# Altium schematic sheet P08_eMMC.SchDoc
size 386 x 246 mm
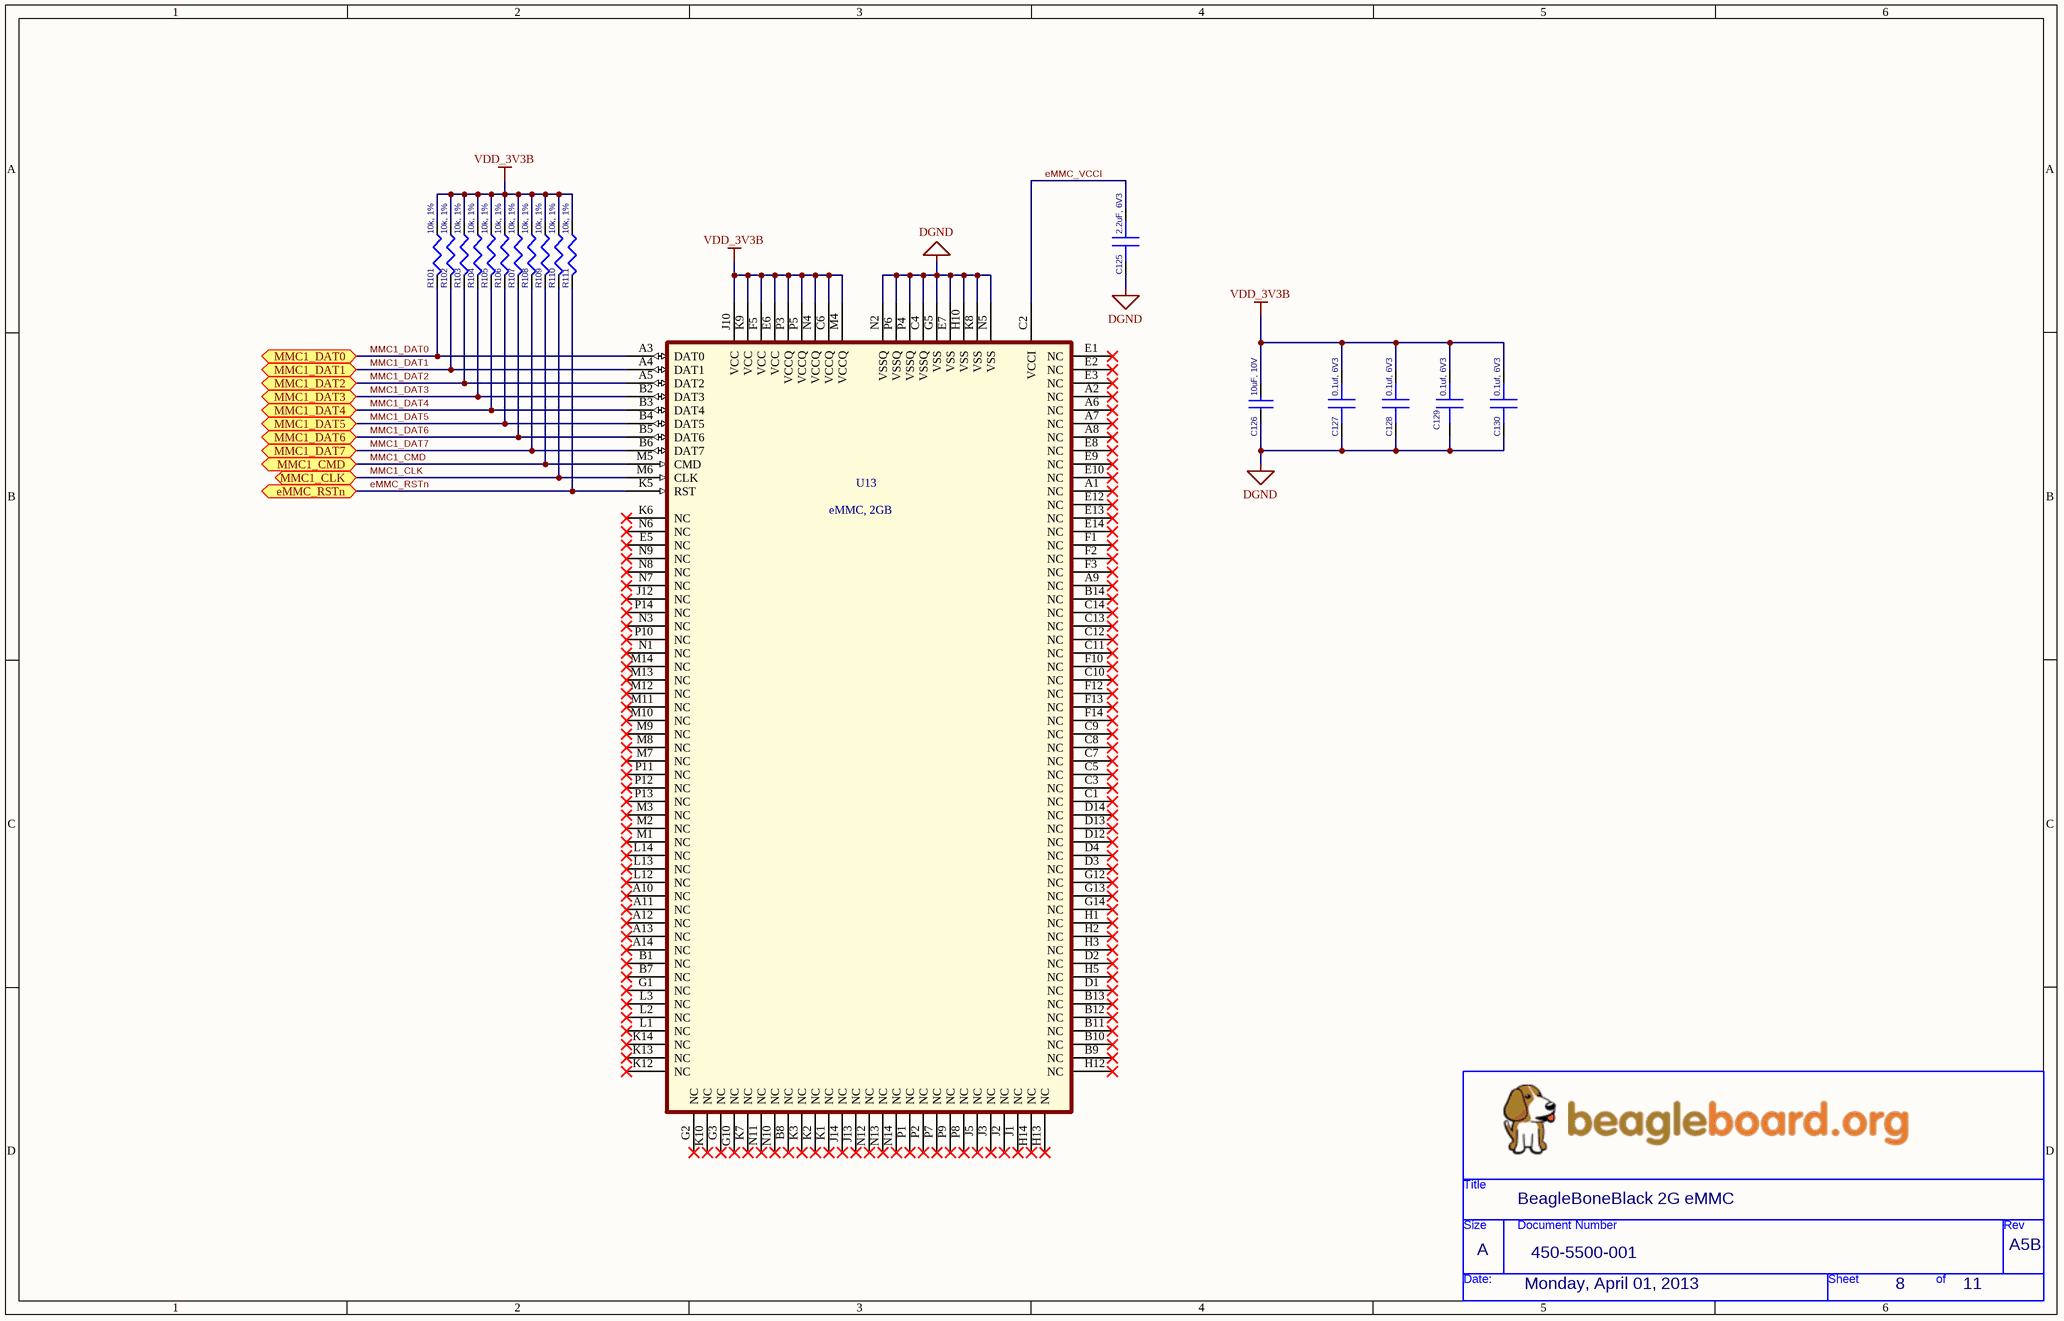
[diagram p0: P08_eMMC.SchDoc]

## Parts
*  Page Create Date: Monday, April 01, 2013  Doc: 450-5500-001  RevCode: A5B  Title: BeagleBoneBlack 2G eMMC  Page Size: A  Page Number: 8  Page Count: 11  (hidden comment: BeagleBoard_org)  (graphical)
C125  2.2uF, 6V3  [402]
C126  10uF, 10V  [805]
C127  0.1uf, 6V3  [402]
C128  0.1uf, 6V3  [402]
C129  0.1uf, 6V3  [402]
C130  0.1uf, 6V3  [402]
R101  10k, 1%  [402]
R102  10k, 1%  [402]
R103  10k, 1%  [402]
R104  10k, 1%  [402]
R105  10k, 1%  [402]
R106  10k, 1%  [402]
R107  10k, 1%  [402]
R108  10k, 1%  [402]
R109  10k, 1%  [402]
R110  10k, 1%  [402]
R111  10k, 1%  [402]
U13  eMMC, 2GB  [BGA153_P14_P5_11P5X13]

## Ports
eMMC_RSTn, MMC1_CLK, MMC1_CMD, MMC1_DAT0, MMC1_DAT1, MMC1_DAT2, MMC1_DAT3, MMC1_DAT4, MMC1_DAT5, MMC1_DAT6, MMC1_DAT7

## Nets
DGND: C125.2 C126.1 C127.2 C128.2 C129.2 C130.2 U13.C4(VSSQ) U13.E7(VSS) U13.G5(VSS) U13.H10(VSS) U13.K8(VSS) U13.N2(VSSQ) U13.N5(VSS) U13.P4(VSSQ) U13.P6(VSSQ)
VDD_3V3B: C126.2 C127.1 C128.1 C129.1 C130.1 R101.1 R102.1 R103.1 R104.1 R105.1 R106.1 R107.1 R108.1 R109.1 R110.1 R111.1 U13.C6(VCCQ) U13.E6(VCC) U13.F5(VCC) U13.J10(VCC) U13.K9(VCC) U13.M4(VCCQ) U13.N4(VCCQ) U13.P3(VCCQ) U13.P5(VCCQ)
eMMC_RSTn: R111.2 U13.K5(RST) ; port eMMC_RSTn
eMMC_VCCI: C125.1 U13.C2(VCCI)
MMC1_CLK: R110.2 U13.M6(CLK) ; port MMC1_CLK
MMC1_CMD: R109.2 U13.M5(CMD) ; port MMC1_CMD
MMC1_DAT0: R101.2 U13.A3(DAT0) ; port MMC1_DAT0
MMC1_DAT1: R102.2 U13.A4(DAT1) ; port MMC1_DAT1
MMC1_DAT2: R103.2 U13.A5(DAT2) ; port MMC1_DAT2
MMC1_DAT3: R104.2 U13.B2(DAT3) ; port MMC1_DAT3
MMC1_DAT4: R105.2 U13.B3(DAT4) ; port MMC1_DAT4
MMC1_DAT5: R106.2 U13.B4(DAT5) ; port MMC1_DAT5
MMC1_DAT6: R107.2 U13.B5(DAT6) ; port MMC1_DAT6
MMC1_DAT7: R108.2 U13.B6(DAT7) ; port MMC1_DAT7

Not connected (* = marked no-connect by the designer): U13 A1(NC)* A2(NC)* A6(NC)* A7(NC)* A8(NC)* A9(NC)* A10(NC)* A11(NC)* A12(NC)* A13(NC)* A14(NC)* B1(NC)* B7(NC)* B8(NC)* B9(NC)* B10(NC)* B11(NC)* B12(NC)* B13(NC)* B14(NC)* C1(NC)* C3(NC)* C5(NC)* C7(NC)* C8(NC)* C9(NC)* C10(NC)* C11(NC)* C12(NC)* C13(NC)* C14(NC)* D1(NC)* D2(NC)* D3(NC)* D4(NC)* D12(NC)* D13(NC)* D14(NC)* E1(NC)* E2(NC)* E3(NC)* E5(NC)* E8(NC)* E9(NC)* E10(NC)* E12(NC)* E13(NC)* E14(NC)* F1(NC)* F2(NC)* F3(NC)* F10(NC)* F12(NC)* F13(NC)* F14(NC)* G1(NC)* G2(NC)* G3(NC)* G10(NC)* G12(NC)* G13(NC)* G14(NC)* H1(NC)* H2(NC)* H3(NC)* H5(NC)* H12(NC)* H13(NC)* H14(NC)* J1(NC)* J2(NC)* J3(NC)* J5(NC)* J12(NC)* J13(NC)* J14(NC)* K1(NC)* K2(NC)* K3(NC)* K6(NC)* K7(NC)* K10(NC)* K12(NC)* K13(NC)* K14(NC)* L1(NC)* L2(NC)* L3(NC)* L12(NC)* L13(NC)* L14(NC)* M1(NC)* M2(NC)* M3(NC)* M7(NC)* M8(NC)* M9(NC)* M10(NC)* M11(NC)* M12(NC)* M13(NC)* M14(NC)* N1(NC)* N3(NC)* N6(NC)* N7(NC)* N8(NC)* N9(NC)* N10(NC)* N11(NC)* N12(NC)* N13(NC)* N14(NC)* P1(NC)* P2(NC)* P7(NC)* P8(NC)* P9(NC)* P10(NC)* P11(NC)* P12(NC)* P13(NC)* P14(NC)*

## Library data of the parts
C125 = CAP SMD: CAP CER 2.2UF 6.3V 10% X5R 0402; Manufacturer: TDK Corporation; Manufacturer Part Number: C1005X5R0J225K050BC; Capacitance: 2.2µF
C126 = CAP_4.7uF_X5R_6.3V_10%_0603: CAP CER 10UF 10V Y5V 0805; Manufacturer: TDK Corporation; Manufacturer Part Number: C2012Y5V1A106Z; Capacitance: 10µF; Tolerance: -20%, +80%; Temperature Coefficient: Y5V (F)
C127-C130 = CAP SMD: CAP CER 0.1UF 6.3V 10% X5R 0402; Manufacturer: TDK Corporation; Manufacturer Part Number: C1005X5R0J104K050BA; Capacitance: 0.1µF
R101-R111 = RES_10K_1/16W_1%_0402: RES 10K OHM 1/16W 5% 0402 SMD; Manufacturer: Rohm Semiconductor; Manufacturer Part Number: MCR01MZPJ103; Power (Watts): 0.063W, 1/16W; Temperature Coefficient: ±200ppm/°C
U13 = eMMC: Flash Card 2G-byte 3.3V MultiMedia Card 153-Pin WFBGA; Manufacturer: Micron Technology; Manufacturer Part Number: MTFC2GMVEA-0M WT; Lead Time: 2 weeks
